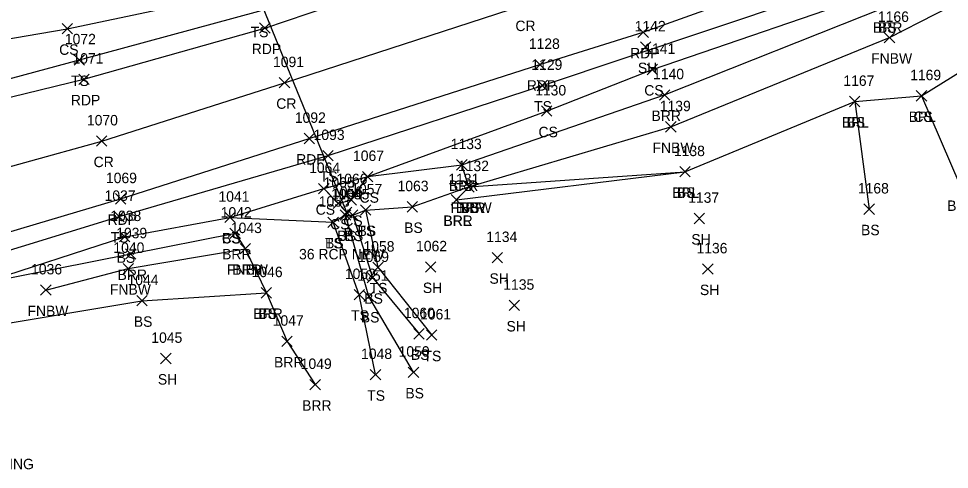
# Model space of a CAD drawing. Extents: x 1443064 to 1445163, y 544063 to 544655.
# Drawn here: x 1443153.5 to 1443332.1, y 544065.3 to 544151.7 of the extents above; entities that cross this region are included whole.
import ezdxf

# ---------------------------------------------------------------- set-up
doc = ezdxf.new("R2010")
doc.units = 0
for name, color, linetype in [('D_A', 7, 'Continuous'), ('D_C', 7, 'Continuous'), ('D_I', 7, 'Continuous'), ('D_TIC', 7, 'Continuous'), ('DCP', 7, 'Continuous'), ('L_A', 7, 'Continuous'), ('L_I', 7, 'Continuous'), ('L_TIC', 7, 'Continuous'), ('LABL', 7, 'Continuous'), ('LELB', 7, 'Continuous'), ('LFNC', 7, 'Continuous'), ('M_C', 7, 'Continuous'), ('P_A', 7, 'Continuous'), ('P_I', 7, 'Continuous'), ('P_TIC', 7, 'Continuous'), ('PET', 7, 'Continuous'), ('PRC', 7, 'Continuous')]:
    doc.layers.add(name, color=color, linetype=linetype)

msp = doc.modelspace()

# ---------------------------------------------------------------- linework, layer by layer
at = {"layer": 'D_TIC'}
for points in [[(1443215.42, 544113.54), (1443217.42, 544115.54)], [(1443217.42, 544113.54), (1443215.42, 544115.54)]]:
    msp.add_lwpolyline(points, dxfattribs=at)
at = {"layer": 'DCP'}
msp.add_lwpolyline([(1443216.42, 544114.54), (1443194.97, 544167.11)], dxfattribs=at)
at = {"layer": 'L_TIC'}
for points in [[(1443161.8, 544148.75), (1443163.8, 544150.75)], [(1443163.8, 544148.75), (1443161.8, 544150.75)], [(1443319.57, 544147.06), (1443321.57, 544149.06)], [(1443321.57, 544147.06), (1443319.57, 544149.06)], [(1443272.8, 544145.25), (1443274.8, 544147.25)], [(1443274.8, 544145.25), (1443272.8, 544147.25)], [(1443164.11, 544142.77), (1443166.11, 544144.77)], [(1443166.11, 544142.77), (1443164.11, 544144.77)], [(1443274.08, 544140.94), (1443276.08, 544142.94)], [(1443276.08, 544140.94), (1443274.08, 544142.94)], [(1443252.97, 544137.87), (1443254.97, 544139.87)], [(1443254.97, 544137.87), (1443252.97, 544139.87)], [(1443276.41, 544136.07), (1443278.41, 544138.07)], [(1443278.41, 544136.07), (1443276.41, 544138.07)], [(1443312.89, 544134.8), (1443314.89, 544136.8)], [(1443314.89, 544134.8), (1443312.89, 544136.8)], [(1443312.89, 544134.8), (1443314.89, 544136.8)], [(1443314.89, 544134.8), (1443312.89, 544136.8)], [(1443325.71, 544135.88), (1443327.71, 544137.88)], [(1443327.71, 544135.88), (1443325.71, 544137.88)], [(1443325.71, 544135.88), (1443327.71, 544137.88)], [(1443327.71, 544135.88), (1443325.71, 544137.88)], [(1443253.78, 544132.96), (1443255.78, 544134.96)], [(1443255.78, 544132.96), (1443253.78, 544134.96)], [(1443277.62, 544129.94), (1443279.62, 544131.94)], [(1443279.62, 544129.94), (1443277.62, 544131.94)], [(1443211.83, 544124.42), (1443213.83, 544126.42)], [(1443213.83, 544124.42), (1443211.83, 544126.42)], [(1443237.51, 544122.67), (1443239.51, 544124.67)], [(1443239.51, 544122.67), (1443237.51, 544124.67)], [(1443237.51, 544122.67), (1443239.51, 544124.67)], [(1443239.51, 544122.67), (1443237.51, 544124.67)], [(1443219.44, 544120.4), (1443221.44, 544122.4)], [(1443221.44, 544120.4), (1443219.44, 544122.4)], [(1443219.44, 544120.4), (1443221.44, 544122.4)], [(1443221.44, 544120.4), (1443219.44, 544122.4)], [(1443280.32, 544121.33), (1443282.32, 544123.33)], [(1443282.32, 544121.33), (1443280.32, 544123.33)], [(1443280.32, 544121.33), (1443282.32, 544123.33)], [(1443282.32, 544121.33), (1443280.32, 544123.33)], [(1443238.88, 544118.45), (1443240.88, 544120.45)], [(1443240.88, 544118.45), (1443238.88, 544120.45)], [(1443238.88, 544118.45), (1443240.88, 544120.45)], [(1443240.88, 544118.45), (1443238.88, 544120.45)], [(1443238.88, 544118.45), (1443240.88, 544120.45)], [(1443240.88, 544118.45), (1443238.88, 544120.45)], [(1443211.02, 544118.1), (1443213.02, 544120.1)], [(1443213.02, 544118.1), (1443211.02, 544120.1)], [(1443211.02, 544118.1), (1443213.02, 544120.1)], [(1443213.02, 544118.1), (1443211.02, 544120.1)], [(1443213.8, 544115.28), (1443215.8, 544117.28)], [(1443215.8, 544115.28), (1443213.8, 544117.28)], [(1443216.32, 544115.96), (1443218.32, 544117.96)], [(1443218.32, 544115.96), (1443216.32, 544117.96)], [(1443236.46, 544115.95), (1443238.46, 544117.95)], [(1443238.46, 544115.95), (1443236.46, 544117.95)], [(1443236.46, 544115.95), (1443238.46, 544117.95)], [(1443238.46, 544115.95), (1443236.46, 544117.95)], [(1443215.18, 544113.05), (1443217.18, 544115.05)], [(1443217.18, 544113.05), (1443215.18, 544115.05)], [(1443215.18, 544113.05), (1443217.18, 544115.05)], [(1443217.18, 544113.05), (1443215.18, 544115.05)], [(1443216.58, 544113.04), (1443218.58, 544115.04)], [(1443218.58, 544113.04), (1443216.58, 544115.04)], [(1443216.58, 544113.04), (1443218.58, 544115.04)], [(1443218.58, 544113.04), (1443216.58, 544115.04)], [(1443219.05, 544114), (1443221.05, 544116)], [(1443221.05, 544114), (1443219.05, 544116)], [(1443219.05, 544114), (1443221.05, 544116)], [(1443221.05, 544114), (1443219.05, 544116)], [(1443227.99, 544114.61), (1443229.99, 544116.61)], [(1443229.99, 544114.61), (1443227.99, 544116.61)], [(1443315.67, 544114.17), (1443317.67, 544116.17)], [(1443317.67, 544114.17), (1443315.67, 544116.17)], [(1443171.72, 544112.76), (1443173.72, 544114.76)], [(1443173.72, 544112.76), (1443171.72, 544114.76)], [(1443193, 544112.59), (1443195, 544114.59)], [(1443195, 544112.59), (1443193, 544114.59)], [(1443193, 544112.59), (1443195, 544114.59)], [(1443195, 544112.59), (1443193, 544114.59)], [(1443212.82, 544111.65), (1443214.82, 544113.65)], [(1443214.82, 544111.65), (1443212.82, 544113.65)], [(1443212.82, 544111.65), (1443214.82, 544113.65)], [(1443214.82, 544111.65), (1443212.82, 544113.65)], [(1443283.06, 544112.38), (1443285.06, 544114.38)], [(1443285.06, 544112.38), (1443283.06, 544114.38)], [(1443194.01, 544109.55), (1443196.01, 544111.55)], [(1443196.01, 544109.55), (1443194.01, 544111.55)], [(1443172.82, 544108.88), (1443174.82, 544110.88)], [(1443174.82, 544108.88), (1443172.82, 544110.88)], [(1443195.95, 544106.58), (1443197.95, 544108.58)], [(1443197.95, 544106.58), (1443195.95, 544108.58)], [(1443195.95, 544106.58), (1443197.95, 544108.58)], [(1443197.95, 544106.58), (1443195.95, 544108.58)], [(1443173.96, 544105.59), (1443175.96, 544107.59)], [(1443175.96, 544105.59), (1443173.96, 544107.59)], [(1443244.32, 544104.87), (1443246.32, 544106.87)], [(1443246.32, 544104.87), (1443244.32, 544106.87)], [(1443173.49, 544102.78), (1443175.49, 544104.78)], [(1443175.49, 544102.78), (1443173.49, 544104.78)], [(1443221.4, 544103.03), (1443223.4, 544105.03)], [(1443223.4, 544103.03), (1443221.4, 544105.03)], [(1443231.54, 544103.09), (1443233.54, 544105.09)], [(1443233.54, 544103.09), (1443231.54, 544105.09)], [(1443284.72, 544102.69), (1443286.72, 544104.69)], [(1443286.72, 544102.69), (1443284.72, 544104.69)], [(1443220.35, 544101.04), (1443222.35, 544103.04)], [(1443222.35, 544101.04), (1443220.35, 544103.04)], [(1443157.68, 544098.66), (1443159.68, 544100.66)], [(1443159.68, 544098.66), (1443157.68, 544100.66)], [(1443200, 544098.13), (1443202, 544100.13)], [(1443202, 544098.13), (1443200, 544100.13)], [(1443200, 544098.13), (1443202, 544100.13)], [(1443202, 544098.13), (1443200, 544100.13)], [(1443217.83, 544097.77), (1443219.83, 544099.77)], [(1443219.83, 544097.77), (1443217.83, 544099.77)], [(1443219.68, 544097.44), (1443221.68, 544099.44)], [(1443221.68, 544097.44), (1443219.68, 544099.44)], [(1443176.12, 544096.61), (1443178.12, 544098.61)], [(1443178.12, 544096.61), (1443176.12, 544098.61)], [(1443247.59, 544095.72), (1443249.59, 544097.72)], [(1443249.59, 544095.72), (1443247.59, 544097.72)], [(1443229.29, 544090.27), (1443231.29, 544092.27)], [(1443231.29, 544090.27), (1443229.29, 544092.27)], [(1443231.74, 544090.02), (1443233.74, 544092.02)], [(1443233.74, 544090.02), (1443231.74, 544092.02)], [(1443203.98, 544088.82), (1443205.98, 544090.82)], [(1443205.98, 544088.82), (1443203.98, 544090.82)], [(1443180.7, 544085.54), (1443182.7, 544087.54)], [(1443182.7, 544085.54), (1443180.7, 544087.54)], [(1443228.23, 544082.89), (1443230.23, 544084.89)], [(1443230.23, 544082.89), (1443228.23, 544084.89)], [(1443220.94, 544082.44), (1443222.94, 544084.44)], [(1443222.94, 544082.44), (1443220.94, 544084.44)], [(1443209.37, 544080.53), (1443211.37, 544082.53)], [(1443211.37, 544080.53), (1443209.37, 544082.53)]]:
    msp.add_lwpolyline(points, dxfattribs=at)
at = {"layer": 'LABL'}
for points in [[(1443237.46, 544116.95), (1443239.88, 544119.45), (1443238.51, 544123.67), (1443277.41, 544137.07), (1443319.92, 544153.98), (1443347.34, 544164.94), (1443351.22, 544161.82), (1443356.07, 544155.13), (1443361.46, 544147.05)], [(1443237.46, 544116.95), (1443281.32, 544122.33), (1443313.89, 544135.8), (1443326.71, 544136.88), (1443334.1, 544119.83)], [(1443135.09, 544080.94), (1443148.23, 544086.26), (1443147.52, 544092.64), (1443146.21, 544100.93), (1443174.96, 544106.59), (1443195.01, 544110.55), (1443196.95, 544107.58), (1443201, 544099.13), (1443204.98, 544089.82), (1443210.37, 544081.53)]]:
    msp.add_lwpolyline(points, dxfattribs=at)
at = {"layer": 'LELB'}
for points in [[(1443073.59, 544128.34), (1443116.66, 544141.89), (1443162.8, 544149.75), (1443198.07, 544157.24), (1443242.5, 544173.41), (1443262.84, 544182.05), (1443307.11, 544199.46), (1443348.85, 544214.35), (1443394.74, 544233.02), (1443435.02, 544243.93), (1443473.16, 544259.47), (1443514.32, 544272.16), (1443555.56, 544285.54), (1443605.06, 544302.52), (1443644.56, 544313.72), (1443676.09, 544324.26), (1443689.45, 544326.75), (1443708.55, 544330.01), (1443714.07, 544333.45), (1443742.84, 544349.83), (1443793.92, 544368.99), (1443822.61, 544377.56)], [(1443074.67, 544122.4), (1443120.32, 544131.74), (1443165.11, 544143.77), (1443199.58, 544153.13), (1443245.24, 544167.88), (1443264.59, 544177.57), (1443308.86, 544194.48), (1443350.56, 544209.36), (1443397.32, 544225.82), (1443437.1, 544238.98), (1443476.53, 544253.14), (1443516.75, 544265.8), (1443558.95, 544280.95), (1443607.52, 544296.39), (1443646.45, 544306.32), (1443685.12, 544319.06), (1443714.26, 544329.16), (1443721.31, 544331.26), (1443744.28, 544345.57), (1443795.65, 544366.53), (1443822.61, 544377.56)], [(1443082.68, 544086.51), (1443130.13, 544099.67), (1443144.13, 544104.98), (1443172.72, 544113.76), (1443212.83, 544125.42), (1443253.97, 544138.87), (1443319.39, 544160.76), (1443361, 544176.06), (1443409.52, 544193.8), (1443447.54, 544206.03), (1443485.93, 544218.99), (1443527.17, 544233.73), (1443570.65, 544246.93), (1443621.44, 544264.66), (1443656.15, 544276.08), (1443695.78, 544288.38), (1443720.36, 544296.79), (1443749.28, 544306.83), (1443759.63, 544310.57), (1443806.78, 544328.14), (1443835.8, 544338.24)], [(1443326.71, 544136.88), (1443356.07, 544155.13), (1443385.8, 544161.03), (1443414.14, 544171.77), (1443454.43, 544184.84), (1443493.74, 544198.5), (1443535.62, 544210.92), (1443545.67, 544211.73), (1443551.85, 544201.5), (1443566.51, 544204.54), (1443590.28, 544210.64), (1443632.95, 544239.56)], [(1443194, 544113.59), (1443212.02, 544119.1), (1443220.44, 544121.4), (1443254.78, 544133.96), (1443275.08, 544141.94), (1443320.32, 544157.47), (1443361.38, 544174.3)], [(1443313.89, 544135.8), (1443316.67, 544115.17)], [(1443083.51, 544082.64), (1443130.86, 544097.05), (1443146.21, 544100.93), (1443173.82, 544109.88), (1443194, 544113.59), (1443213.82, 544112.65), (1443216.18, 544114.05), (1443217.58, 544114.04), (1443220.05, 544115), (1443228.99, 544115.61), (1443239.88, 544119.45), (1443281.32, 544122.33)], [(1443212.02, 544119.1), (1443214.8, 544116.28), (1443217.32, 544116.96), (1443220.44, 544121.4), (1443238.51, 544123.67)], [(1443229.23, 544083.89), (1443220.68, 544098.44), (1443216.18, 544114.05)], [(1443217.58, 544114.04), (1443221.35, 544102.04), (1443230.29, 544091.27)], [(1443220.05, 544115), (1443222.4, 544104.03), (1443232.74, 544091.02)], [(1443221.94, 544083.44), (1443218.83, 544098.77), (1443213.82, 544112.65)], [(1443084.81, 544077.17), (1443133.27, 544090.26), (1443147.52, 544092.64), (1443177.12, 544097.61), (1443201, 544099.13)]]:
    msp.add_lwpolyline(points, dxfattribs=at)
at = {"layer": 'LFNC'}
for points in [[(1443239.88, 544119.45), (1443278.62, 544130.94), (1443320.57, 544148.06), (1443338.13, 544157.08), (1443351.22, 544161.82), (1443363.5, 544166.21), (1443412.24, 544182.91), (1443449.91, 544194.79), (1443489.63, 544207.22), (1443534.54, 544218.89), (1443545.24, 544222.13), (1443555.28, 544222.99), (1443566.76, 544221.91), (1443584.49, 544223.6), (1443632.95, 544239.56), (1443668.35, 544248.03), (1443707.08, 544263.81), (1443742.56, 544273.31)], [(1443158.68, 544099.66), (1443174.49, 544103.78), (1443196.95, 544107.58)]]:
    msp.add_lwpolyline(points, dxfattribs=at)
at = {"layer": 'P_TIC'}
for points in [[(1443199.71, 544148.88), (1443201.71, 544150.88)], [(1443201.71, 544148.88), (1443199.71, 544150.88)], [(1443272.3, 544148.07), (1443274.3, 544150.07)], [(1443274.3, 544148.07), (1443272.3, 544150.07)], [(1443252.49, 544141.88), (1443254.49, 544143.88)], [(1443254.49, 544141.88), (1443252.49, 544143.88)], [(1443164.99, 544139.07), (1443166.99, 544141.07)], [(1443166.99, 544139.07), (1443164.99, 544141.07)], [(1443203.47, 544138.4), (1443205.47, 544140.4)], [(1443205.47, 544138.4), (1443203.47, 544140.4)], [(1443208.23, 544127.71), (1443210.23, 544129.71)], [(1443210.23, 544127.71), (1443208.23, 544129.71)], [(1443168.41, 544127.22), (1443170.41, 544129.22)], [(1443170.41, 544127.22), (1443168.41, 544129.22)], [(1443172.03, 544116.15), (1443174.03, 544118.15)], [(1443174.03, 544116.15), (1443172.03, 544118.15)]]:
    msp.add_lwpolyline(points, dxfattribs=at)
at = {"layer": 'PET'}
for points in [[(1443075.39, 544117.71), (1443121.41, 544129.24), (1443165.99, 544140.07), (1443200.71, 544149.88), (1443246.42, 544165.39), (1443265.96, 544172.48), (1443311.2, 544187.88), (1443352.92, 544202.76), (1443399.28, 544220.13), (1443438.78, 544233.67), (1443478.75, 544247.35), (1443518.41, 544260.6), (1443561.23, 544274.05), (1443611.7, 544290.5), (1443646.84, 544301.68), (1443684.98, 544314.55), (1443724.57, 544327.54), (1443735.41, 544331.22), (1443748.81, 544336.36), (1443799.43, 544353.96), (1443827.31, 544364.14)], [(1443081.93, 544089.54), (1443128.67, 544104.01), (1443173.03, 544117.15), (1443209.23, 544128.71), (1443253.49, 544142.88), (1443273.3, 544149.07), (1443318.27, 544165.2), (1443359.78, 544179.84), (1443408.54, 544196.96), (1443445.92, 544210.12), (1443484.92, 544223.61), (1443525.67, 544237.02), (1443568.63, 544251.04), (1443620.57, 544267.93), (1443654.52, 544278.93), (1443694.69, 544292.43), (1443717.24, 544299.44), (1443752.8, 544310.97), (1443757.72, 544314.31), (1443805.74, 544330.07), (1443835.35, 544341.18)]]:
    msp.add_lwpolyline(points, dxfattribs=at)
at = {"layer": 'PRC'}
msp.add_lwpolyline([(1443078.47, 544103.68), (1443125.02, 544115.93), (1443169.41, 544128.22), (1443204.47, 544139.4), (1443250.36, 544154.3), (1443269.99, 544160.83), (1443315.13, 544176.71), (1443356.58, 544191.19), (1443403.59, 544208.05), (1443442.67, 544222.02), (1443482.15, 544235.41), (1443522.16, 544248.37), (1443565.47, 544262.64), (1443616.51, 544279.34), (1443650.9, 544289.93), (1443689.58, 544302.53), (1443728.44, 544315.77), (1443753.53, 544324.68), (1443803.56, 544342.2), (1443830.96, 544352.16)], dxfattribs=at)

# ---------------------------------------------------------------- texts
at = {"layer": 'D_A'}
msp.add_text('P', height=2, dxfattribs=at).set_placement((1443215.8, 544109.54))
at = {"layer": 'D_C'}
msp.add_text('36 RCP NEW', height=2, dxfattribs=at).set_placement((1443207.27, 544105.54))
at = {"layer": 'D_I'}
msp.add_text('1056', height=2, dxfattribs=at).set_placement((1443213.6, 544117.54))
at = {"layer": 'L_A'}
for s, p in [('BRR', (1443317.41, 544148.98)), ('BS', (1443318.36, 544148.98)), ('TS', (1443197.99, 544148.13)), ('CS', (1443161.24, 544144.75)), ('FNBW', (1443317.05, 544143.06)), ('SH', (1443272.29, 544141.25)), ('TS', (1443163.52, 544138.77)), ('CS', (1443273.52, 544136.94)), ('TS', (1443252.38, 544133.87)), ('BRR', (1443274.9, 544132.07)), ('BRL', (1443324.26, 544131.88)), ('CS', (1443325.16, 544131.88)), ('BRL', (1443311.43, 544130.8)), ('BS', (1443312.33, 544130.8)), ('CS', (1443253.22, 544128.96)), ('FNBW', (1443275.09, 544125.94)), ('TS', (1443211.24, 544120.42)), ('BRR', (1443236, 544118.67)), ('CS', (1443236.95, 544118.67)), ('BRL', (1443278.87, 544117.33)), ('BS', (1443279.76, 544117.33)), ('CS', (1443218.88, 544116.4)), ('CS', (1443218.88, 544116.4)), ('BRL', (1443331.64, 544114.83)), ('CS', (1443210.46, 544114.1)), ('CS', (1443210.46, 544114.1)), ('FNBW', (1443236.36, 544114.45)), ('BRR', (1443237.37, 544114.45)), ('BS', (1443238.32, 544114.45)), ('CS', (1443213.24, 544111.28)), ('CS', (1443215.76, 544111.96)), ('BRR', (1443234.94, 544111.95)), ('BRL', (1443235, 544111.95)), ('TS', (1443218.46, 544110)), ('BS', (1443218.49, 544110)), ('BS', (1443227.43, 544110.61)), ('BS', (1443315.11, 544110.17)), ('TS', (1443171.13, 544108.76)), ('CS', (1443192.44, 544108.59)), ('BS', (1443192.44, 544108.59)), ('TS', (1443212.23, 544107.65)), ('BS', (1443212.26, 544107.65)), ('BS', (1443214.62, 544109.05)), ('BS', (1443214.62, 544109.05)), ('BS', (1443216.02, 544109.04)), ('BS', (1443216.02, 544109.04)), ('SH', (1443282.55, 544108.38)), ('BS', (1443172.26, 544104.88)), ('BRR', (1443192.5, 544105.55)), ('FNBW', (1443193.42, 544102.58)), ('BRR', (1443194.44, 544102.58)), ('BRR', (1443172.45, 544101.59)), ('SH', (1443243.81, 544100.87)), ('FNBW', (1443170.97, 544098.78)), ('TS', (1443220.81, 544099.03)), ('SH', (1443231.03, 544099.09)), ('SH', (1443284.2, 544098.69)), ('BS', (1443219.79, 544097.04)), ('FNBW', (1443155.15, 544094.66)), ('BRR', (1443198.49, 544094.13)), ('BS', (1443199.44, 544094.13)), ('TS', (1443217.24, 544093.77)), ('BS', (1443219.12, 544093.44)), ('BS', (1443175.56, 544092.61)), ('SH', (1443247.08, 544091.72)), ('BS', (1443228.73, 544086.27)), ('BRR', (1443202.47, 544084.82)), ('TS', (1443231.15, 544086.02)), ('SH', (1443180.18, 544081.54)), ('TS', (1443220.35, 544078.44)), ('BS', (1443227.67, 544078.89)), ('BRR', (1443207.86, 544076.53))]:
    msp.add_text(s, height=2, dxfattribs=at).set_placement(p)
at = {"layer": 'L_I'}
for s, p in [('1166', (1443318.35, 544151.06)), ('1142', (1443271.68, 544149.25)), ('1072', (1443162.33, 544146.77)), ('1141', (1443273.52, 544144.94)), ('1129', (1443251.84, 544141.87)), ('1140', (1443275.2, 544140.07)), ('1169', (1443324.53, 544139.88)), ('1169', (1443324.53, 544139.88)), ('1167', (1443311.72, 544138.8)), ('1167', (1443311.72, 544138.8)), ('1130', (1443252.57, 544136.96)), ('1139', (1443276.49, 544133.94)), ('1093', (1443210.06, 544128.42)), ('1133', (1443236.38, 544126.67)), ('1133', (1443236.38, 544126.67)), ('1067', (1443217.62, 544124.4)), ('1067', (1443217.62, 544124.4)), ('1138', (1443279.2, 544125.33)), ('1138', (1443279.2, 544125.33)), ('1064', (1443209.2, 544122.1)), ('1064', (1443209.2, 544122.1)), ('1132', (1443237.76, 544122.45)), ('1132', (1443237.76, 544122.45)), ('1132', (1443237.76, 544122.45)), ('1065', (1443211.98, 544119.28)), ('1066', (1443214.45, 544119.96)), ('1063', (1443226.17, 544118.61)), ('1131', (1443235.9, 544119.95)), ('1131', (1443235.9, 544119.95)), ('1037', (1443169.95, 544116.76)), ('1041', (1443191.8, 544116.59)), ('1041', (1443191.8, 544116.59)), ('1054', (1443213.41, 544117.05)), ('1054', (1443213.41, 544117.05)), ('1055', (1443214.81, 544117.04)), ('1055', (1443214.81, 544117.04)), ('1057', (1443217.28, 544118)), ('1057', (1443217.28, 544118)), ('1168', (1443314.5, 544118.17)), ('1053', (1443211.05, 544115.65)), ('1053', (1443211.05, 544115.65)), ('1137', (1443281.94, 544116.38)), ('1042', (1443192.24, 544113.55)), ('1038', (1443171.04, 544112.88)), ('1039', (1443172.18, 544109.59)), ('1043', (1443194.18, 544110.58)), ('1043', (1443194.18, 544110.58)), ('1134', (1443243.2, 544108.87)), ('1040', (1443171.64, 544106.78)), ('1058', (1443219.63, 544107.03)), ('1062', (1443229.72, 544107.09)), ('1136', (1443283.53, 544106.69)), ('1059', (1443218.57, 544105.04)), ('1036', (1443155.85, 544102.66)), ('1044', (1443174.35, 544100.61)), ('1046', (1443198.17, 544102.13)), ('1046', (1443198.17, 544102.13)), ('1052', (1443216.06, 544101.77)), ('1051', (1443218.47, 544101.44)), ('1135', (1443246.46, 544099.72)), ('1060', (1443227.39, 544094.27)), ('1061', (1443230.49, 544094.02)), ('1047', (1443202.21, 544092.82)), ('1045', (1443178.92, 544089.54)), ('1048', (1443219.17, 544086.44)), ('1050', (1443226.37, 544086.89)), ('1049', (1443207.59, 544084.53))]:
    msp.add_text(s, height=2, dxfattribs=at).set_placement(p)
at = {"layer": 'M_C'}
msp.add_text('SURVEY DISK STATE VT STAMPING', height=2, dxfattribs=at).set_placement((1443110.17, 544065.31))
at = {"layer": 'P_A'}
for s, p in [('CR', (1443248.79, 544149.3)), ('RDP', (1443198.19, 544144.88)), ('RDP', (1443270.79, 544144.07)), ('RDP', (1443250.98, 544137.88)), ('RDP', (1443163.48, 544135.07)), ('CR', (1443202.9, 544134.4)), ('CR', (1443167.85, 544123.22)), ('RDP', (1443206.72, 544123.71)), ('RDP', (1443170.52, 544112.15))]:
    msp.add_text(s, height=2, dxfattribs=at).set_placement(p)
at = {"layer": 'P_I'}
for s, p in [('1128', (1443251.36, 544145.88)), ('1071', (1443163.79, 544143.07)), ('1091', (1443202.27, 544142.4)), ('1070', (1443166.56, 544131.22)), ('1092', (1443206.46, 544131.71)), ('1069', (1443170.21, 544120.15))]:
    msp.add_text(s, height=2, dxfattribs=at).set_placement(p)

doc.saveas('drawing.dxf')
